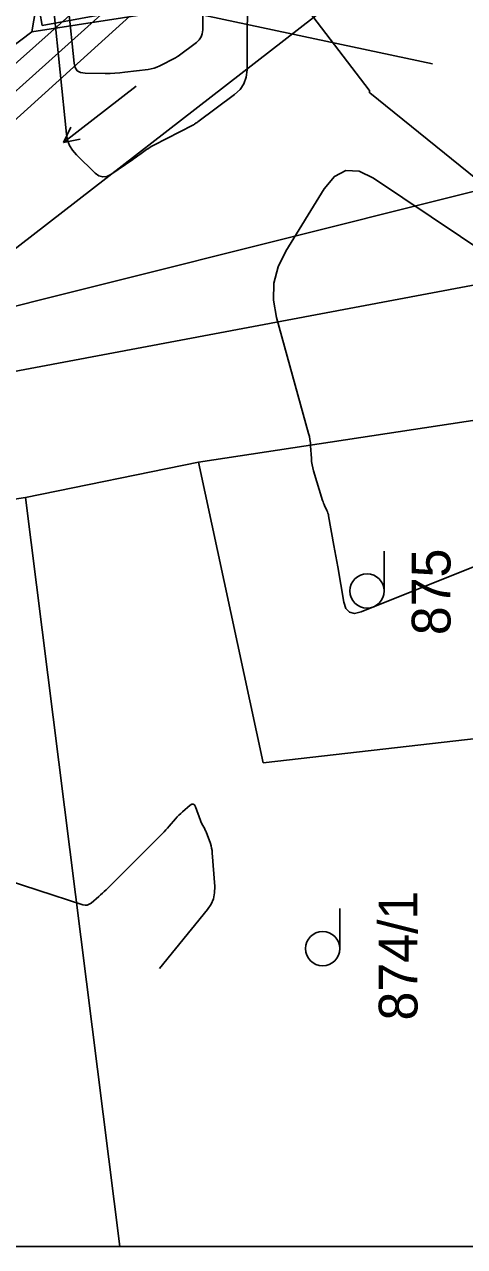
# Model space of a CAD drawing. Extents: x -534410 to -534262, y -1190162 to -1189584.
# Drawn here: x -534329.45 to -534319.81, y -1190161.97 to -1190135.2 of the extents above; entities that cross this region are included whole.
import ezdxf

# ---------------------------------------------------------------- set-up
doc = ezdxf.new("R2010")
doc.units = 0
for name, color, linetype in [('30', 7, 'Continuous'), ('31', 7, 'Continuous'), ('_N_osa', 7, 'Continuous'), ('_N_tenká', 7, 'Continuous'), ('_rámeček', 7, 'Continuous'), ('_rámeček_mřížka', 7, 'Continuous'), ('_tenka', 7, 'Continuous'), ('_tenká_čárkovaná', 7, 'Continuous'), ('Default', 7, 'Continuous'), ('Hranice parcel', 7, 'Continuous'), ('Parcelní čísla', 7, 'Continuous'), ('Vnitřní kresba', 7, 'Continuous'), ('Značky kultur', 7, 'Continuous')]:
    doc.layers.add(name, color=color, linetype=linetype)

msp = doc.modelspace()

# ---------------------------------------------------------------- linework, layer by layer
at = {"layer": '30'}
for points in [[(-534324.566, -1190134.103), (-534324.575, -1190136.191), (-534324.593, -1190136.352), (-534324.645, -1190136.497), (-534324.731, -1190136.624), (-534324.851, -1190136.734), (-534325.654, -1190137.331), (-534325.672, -1190137.344), (-534325.689, -1190137.356), (-534325.725, -1190137.382), (-534325.734, -1190137.388), (-534325.743, -1190137.394), (-534325.753, -1190137.399), (-534325.763, -1190137.404), (-534326.619, -1190137.843), (-534326.66, -1190137.865), (-534326.7, -1190137.889), (-534326.739, -1190137.914), (-534326.777, -1190137.941), (-534326.928, -1190138.05), (-534326.966, -1190138.077), (-534327.004, -1190138.104), (-534327.042, -1190138.131), (-534327.081, -1190138.157), (-534327.558, -1190138.483), (-534327.649, -1190138.528), (-534327.737, -1190138.538), (-534327.822, -1190138.513), (-534327.904, -1190138.453), (-534328.315, -1190138.053), (-534328.401, -1190137.955), (-534328.465, -1190137.848), (-534328.509, -1190137.73), (-534328.533, -1190137.603), (-534328.812, -1190134.889)], [(-534333.115, -1190152.877), (-534328.176, -1190154.481), (-534328.126, -1190154.491), (-534328.078, -1190154.488), (-534328.033, -1190154.473), (-534327.991, -1190154.444), (-534327.826, -1190154.304), (-534327.785, -1190154.268), (-534327.745, -1190154.232), (-534327.705, -1190154.195), (-534327.666, -1190154.157), (-534326.43, -1190152.921), (-534326.392, -1190152.882), (-534326.355, -1190152.843), (-534326.319, -1190152.803), (-534326.284, -1190152.762), (-534326.143, -1190152.597), (-534326.107, -1190152.557), (-534326.07, -1190152.518), (-534326.031, -1190152.48), (-534325.99, -1190152.445), (-534325.826, -1190152.304), (-534325.787, -1190152.28), (-534325.755, -1190152.277), (-534325.728, -1190152.295), (-534325.706, -1190152.336), (-534325.597, -1190152.639), (-534325.588, -1190152.66), (-534325.579, -1190152.682), (-534325.569, -1190152.702), (-534325.558, -1190152.723), (-534325.512, -1190152.804), (-534325.501, -1190152.824), (-534325.491, -1190152.845), (-534325.481, -1190152.867), (-534325.473, -1190152.888), (-534325.381, -1190153.143), (-534325.365, -1190153.193), (-534325.352, -1190153.244), (-534325.343, -1190153.295), (-534325.338, -1190153.348), (-534325.285, -1190154.085), (-534325.287, -1190154.222), (-534325.314, -1190154.35), (-534325.366, -1190154.471), (-534325.442, -1190154.584), (-534326.493, -1190155.876)]]:
    msp.add_lwpolyline(points, dxfattribs=at)
at = {"layer": '31'}
for points in [[(-534325.543, -1190134.297), (-534325.548, -1190135.32), (-534325.557, -1190135.401), (-534325.583, -1190135.473), (-534325.626, -1190135.537), (-534325.686, -1190135.592), (-534326.087, -1190135.89), (-534326.101, -1190135.9), (-534326.123, -1190135.916), (-534326.128, -1190135.919), (-534326.132, -1190135.922), (-534326.137, -1190135.924), (-534326.142, -1190135.927), (-534326.491, -1190136.106), (-534326.552, -1190136.134), (-534326.615, -1190136.157), (-534326.679, -1190136.173), (-534326.745, -1190136.184), (-534327.256, -1190136.247), (-534327.364, -1190136.259), (-534327.471, -1190136.267), (-534327.579, -1190136.271), (-534327.688, -1190136.272), (-534328.127, -1190136.267), (-534328.224, -1190136.253), (-534328.296, -1190136.211), (-534328.344, -1190136.143), (-534328.368, -1190136.048), (-534328.491, -1190134.847)], [(-534323.513, -1190134.518), (-534321.9, -1190136.637), (-534321.897, -1190136.641), (-534321.895, -1190136.646), (-534321.894, -1190136.652), (-534321.894, -1190136.657), (-534321.896, -1190136.68), (-534321.896, -1190136.685), (-534321.894, -1190136.69), (-534321.892, -1190136.694), (-534321.888, -1190136.698), (-534315.946, -1190141.494)], [(-534316.73, -1190141.966), (-534321.806, -1190138.563), (-534322.123, -1190138.411), (-534322.409, -1190138.399), (-534322.664, -1190138.529), (-534322.889, -1190138.799), (-534323.727, -1190140.163), (-534323.897, -1190140.509), (-534323.987, -1190140.867), (-534323.999, -1190141.236), (-534323.932, -1190141.616), (-534323.227, -1190144.159), (-534323.211, -1190144.226), (-534323.198, -1190144.293), (-534323.188, -1190144.361), (-534323.183, -1190144.43), (-534323.167, -1190144.706), (-534323.161, -1190144.775), (-534323.151, -1190144.843), (-534323.137, -1190144.91), (-534323.119, -1190144.977), (-534322.922, -1190145.626), (-534322.912, -1190145.655), (-534322.902, -1190145.683), (-534322.89, -1190145.711), (-534322.878, -1190145.738), (-534322.826, -1190145.847), (-534322.814, -1190145.874), (-534322.803, -1190145.902), (-534322.795, -1190145.931), (-534322.789, -1190145.96), (-534322.672, -1190146.609), (-534322.651, -1190146.727), (-534322.63, -1190146.845), (-534322.609, -1190146.963), (-534322.588, -1190147.081), (-534322.454, -1190147.855), (-534322.409, -1190147.995), (-534322.331, -1190148.076), (-534322.221, -1190148.1), (-534322.078, -1190148.065), (-534317.532, -1190146.248)]]:
    msp.add_lwpolyline(points, dxfattribs=at)
at = {"layer": '_N_osa'}
msp.add_lwpolyline([(-534336.316, -1190142.642), (-534327.357, -1190134.604)], dxfattribs=at)
at = {"layer": '_N_tenká'}
msp.add_line((-534320.511, -1190136.064), (-534334.203, -1190133.144), dxfattribs=at)
at = {"layer": '_rámeček'}
msp.add_lwpolyline([(-534410.126, -1190161.97), (-534261.626, -1190161.97), (-534261.626, -1189584.47)], dxfattribs=at)
at = {"layer": '_rámeček_mřížka'}
msp.add_lwpolyline([(-534410.126, -1190161.97), (-534261.626, -1190161.97), (-534261.626, -1189584.47)], dxfattribs=at)
at = {"layer": '_tenka'}
for points in [[(-534344.053, -1190143.233), (-534334.908, -1190142.684), (-534316.418, -1190138.053)], [(-534345.413, -1190144.601), (-534330.814, -1190143.012), (-534315.851, -1190140.2)]]:
    msp.add_lwpolyline(points, dxfattribs=at)
at = {"layer": '_tenká_čárkovaná'}
for points in [[(-534335.428, -1190142.509), (-534326.521, -1190134.45)], [(-534337.204, -1190142.776), (-534328.194, -1190134.759)]]:
    msp.add_lwpolyline(points, dxfattribs=at)
at = {"layer": 'Default'}
for p, q in [((-534329.066, -1190135.225), (-534323.436, -1190134.185)), ((-534329.12, -1190134.93), (-534329.066, -1190135.225))]:
    msp.add_line(p, q, dxfattribs=at)
at = {"layer": 'Hranice parcel'}
for p, q in [((-534328.71, -1190131.86), (-534329.29, -1190135.36)), ((-534317.35, -1190143.53), (-534325.64, -1190144.79)), ((-534325.64, -1190144.79), (-534329.43, -1190145.56)), ((-534329.43, -1190145.56), (-534337.44, -1190146.76)), ((-534329.43, -1190145.56), (-534327.361, -1190161.97))]:
    msp.add_line(p, q, dxfattribs=at)
for points in [[(-534322.11, -1190134.26), (-534331.87, -1190141.82), (-534341.5, -1190148.5)], [(-534329.29, -1190135.36), (-534326.31, -1190134.9), (-534325.09, -1190134.72), (-534322.11, -1190134.26)], [(-534344.83, -1190147.24), (-534339.41, -1190143.01), (-534329.29, -1190135.36)], [(-534317.38, -1190150.59), (-534324.22, -1190151.37), (-534325.64, -1190144.79)]]:
    msp.add_lwpolyline(points, dxfattribs=at)
at = {"layer": 'Vnitřní kresba'}
for p, q in [((-534329.066, -1190135.225), (-534323.436, -1190134.185)), ((-534329.12, -1190134.93), (-534329.066, -1190135.225))]:
    msp.add_line(p, q, dxfattribs=at)
at = {"layer": 'Značky kultur'}
for p, q in [((-534327.008, -1190136.55), (-534328.596, -1190137.783)), ((-534328.596, -1190137.783), (-534328.44, -1190137.449)), ((-534328.596, -1190137.783), (-534328.234, -1190137.714)), ((-534321.572, -1190147.609), (-534321.572, -1190146.734)), ((-534322.546, -1190155.443), (-534322.546, -1190154.568))]:
    msp.add_line(p, q, dxfattribs=at)
for centre in [(-534321.947, -1190147.609), (-534322.921, -1190155.443)]:
    msp.add_circle(centre, 0.375, dxfattribs=at)

# ---------------------------------------------------------------- texts
at = {"layer": 'Parcelní čísla'}
for s, p in [('875', (-534320.119, -1190148.577)), ('874/1', (-534320.842, -1190157.018))]:
    msp.add_text(s, height=0.85, rotation=90, dxfattribs=at).set_placement(p)

doc.saveas('drawing.dxf')
